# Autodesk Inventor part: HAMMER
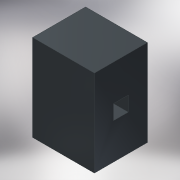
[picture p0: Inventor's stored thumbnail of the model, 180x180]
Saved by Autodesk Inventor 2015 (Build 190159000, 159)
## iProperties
Created: 2014-08
Part Number: HAMMER
Material: Iron, Cast
Document SubType Name: Modeling
Designer: lakshayg
Density: 7.15 g/cm^3
Appearance: Iron Gray
Mass: 1021.47 g
Surface Area: 194.02 cm^2
Volume: 142.863 cm^3
Author: lakshayg
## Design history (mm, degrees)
sketch "Sketch1"
  geometry: L1 (25, 35)-(-25, 35); L2 (-25, -35)-(25, -35); L3 (25, -35)-(25, 35); L4 (25, 35)-(-25, -35); L5 (-25, 35)-(25, -35); L6 (-25, 35)-(-25, -35); 1 further point
  constraints: 12 end point, 2 midpoint, 2 parallel, 1 horizontal, 1 vertical
  dimensions: "d0" = 50 distance of L2.end L2.start; "d9" = 70 distance of L1.end L2.start
extrude "Extrusion1" new body sketch "Sketch1" distance "d2" = 42.8752; taper "d3" = 0 deg
sketch "Sketch2"
  geometry: L1 (0, 0)-(70, 42.875); L2 (0, 42.875)-(70, 0); L3 (29, 15.438)-(41, 15.438); L4 (41, 15.438)-(41, 27.438); L5 (41, 27.438)-(29, 27.438); L6 (29, 27.438)-(29, 15.438); L7 (29, 15.438)-(41, 27.438); L8 (41, 15.438)-(29, 27.438); 1 further point
  constraints: 16 end point, 3 midpoint, 2 parallel, 1 horizontal, 1 perpendicular
  dimensions: "d12" = 12 distance of L5.end L4.end; "d13" = 12 distance of L4.end L3.end
extrude "Extrusion2" cut sketch "Sketch2" stored distance "d6" = 10; taper "d7" = 0 deg
body "Solid1"
